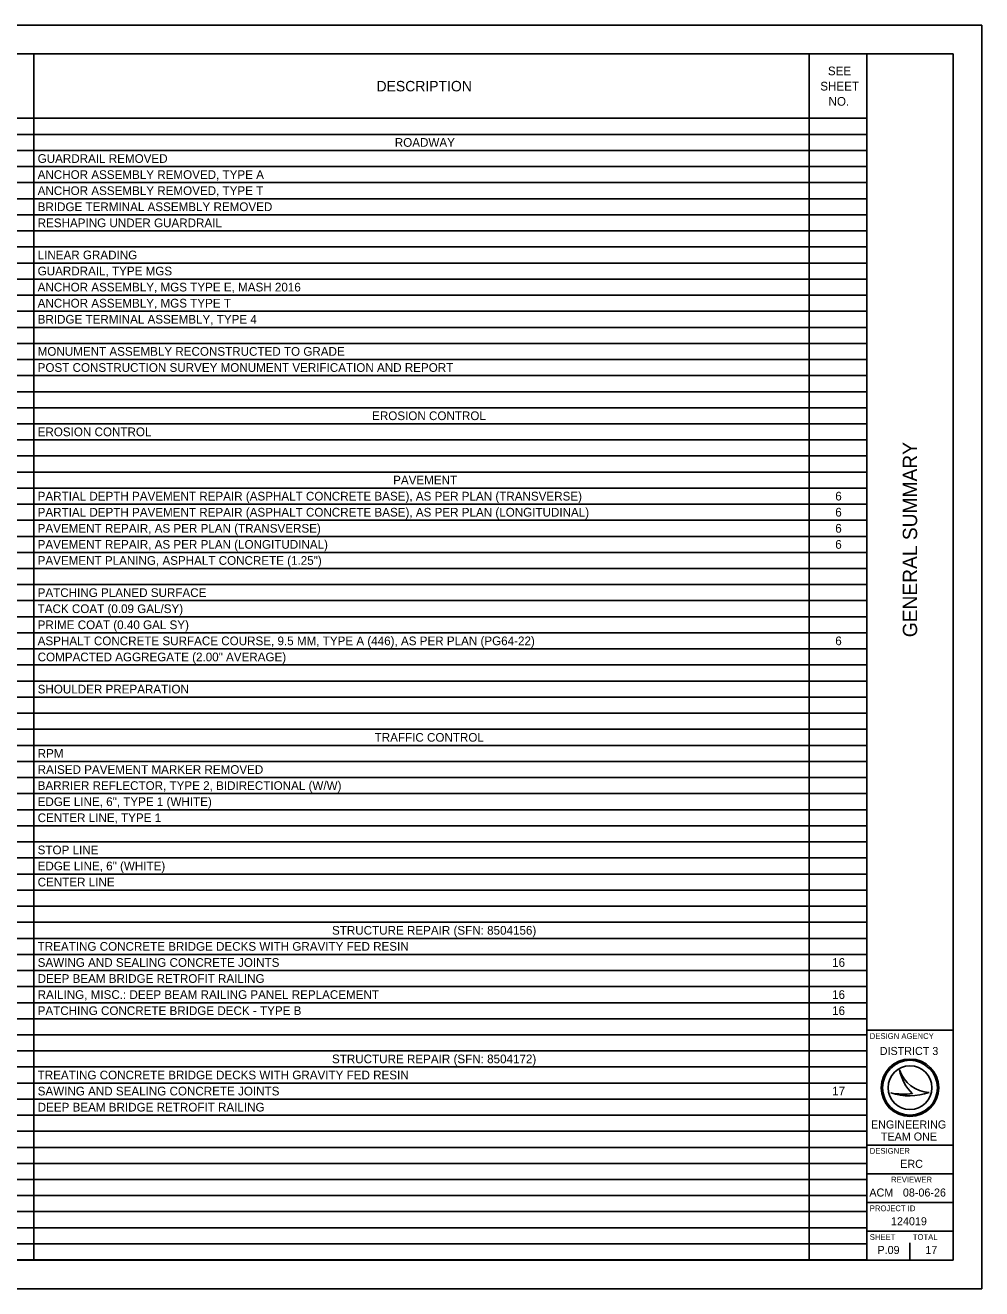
# Model space of a CAD drawing. Extents: x 0 to 34, y 0 to 22.
# Drawn here: x 17.34 to 34, y 0 to 22 of the extents above; entities that cross this region are included whole.
import ezdxf

# ---------------------------------------------------------------- set-up
doc = ezdxf.new("R2010")
doc.units = 0
for name, color, linetype in [('SH_Border', 7, 'Continuous'), ('SH_Cut_Line', 7, 'Continuous'), ('SH_Data', 7, 'Continuous')]:
    doc.layers.add(name, color=color, linetype=linetype)

msp = doc.modelspace()

# ---------------------------------------------------------------- linework, layer by layer
at = {"layer": 'SH_Border'}
for p, q in [((32, 0.5), (32, 21.5)), ((32, 4.5), (33.5, 4.5)), ((32, 2.5), (33.5, 2.5)), ((32, 2), (33.5, 2)), ((32, 1.5), (33.5, 1.5)), ((32, 1), (33.5, 1))]:
    msp.add_line(p, q, dxfattribs=at)
msp.add_lwpolyline([(1.5, 21.5), (33.5, 21.5), (33.5, 0.5), (1.5, 0.5)], close=True, dxfattribs=at)
at = {"layer": 'SH_Cut_Line'}
msp.add_lwpolyline([(0, 0), (34, 0), (34, 22), (0, 22)], close=True, dxfattribs=at)
at = {"layer": 'SH_Data'}
for p, q in [((1.5, 21.5), (32.001, 21.5)), ((17.492, 21.5), (17.492, 0.502)), ((30.997, 21.5), (30.997, 0.502)), ((32.001, 21.5), (32.001, 0.502)), ((1.5, 20.38), (32.001, 20.38)), ((1.5, 20.1), (32.001, 20.1)), ((1.5, 19.82), (32.001, 19.82)), ((1.5, 19.54), (32.001, 19.54)), ((1.5, 19.26), (32.001, 19.26)), ((1.5, 18.98), (32.001, 18.98)), ((1.5, 18.7), (32.001, 18.7)), ((1.5, 18.42), (32.001, 18.42)), ((1.5, 18.14), (32.001, 18.14)), ((1.5, 17.86), (32.001, 17.86)), ((1.5, 17.58), (32.001, 17.58)), ((1.5, 17.3), (32.001, 17.3)), ((1.5, 17.02), (32.001, 17.02)), ((1.5, 16.74), (32.001, 16.74)), ((1.5, 16.46), (32.001, 16.46)), ((1.5, 16.18), (32.001, 16.18)), ((1.5, 15.9), (32.001, 15.9)), ((1.5, 15.62), (32.001, 15.62)), ((1.5, 15.34), (32.001, 15.34)), ((1.5, 15.061), (32.001, 15.061)), ((1.5, 14.781), (32.001, 14.781)), ((1.5, 14.501), (32.001, 14.501)), ((1.5, 14.221), (32.001, 14.221)), ((1.5, 13.941), (32.001, 13.941)), ((1.5, 13.661), (32.001, 13.661)), ((1.5, 13.381), (32.001, 13.381)), ((1.5, 13.101), (32.001, 13.101)), ((1.5, 12.821), (32.001, 12.821)), ((1.5, 12.541), (32.001, 12.541)), ((1.5, 12.261), (32.001, 12.261)), ((1.5, 11.981), (32.001, 11.981)), ((1.5, 11.701), (32.001, 11.701)), ((1.5, 11.421), (32.001, 11.421)), ((1.5, 11.141), (32.001, 11.141)), ((1.5, 10.861), (32.001, 10.861)), ((1.5, 10.581), (32.001, 10.581)), ((1.5, 10.301), (32.001, 10.301)), ((1.5, 10.021), (32.001, 10.021)), ((1.5, 9.741), (32.001, 9.741)), ((1.5, 9.461), (32.001, 9.461)), ((1.5, 9.181), (32.001, 9.181)), ((1.5, 8.901), (32.001, 8.901)), ((1.5, 8.621), (32.001, 8.621)), ((1.5, 8.341), (32.001, 8.341)), ((1.5, 8.061), (32.001, 8.061)), ((1.5, 7.781), (32.001, 7.781)), ((1.5, 7.501), (32.001, 7.501)), ((1.5, 7.221), (32.001, 7.221)), ((1.5, 6.941), (32.001, 6.941)), ((1.5, 6.661), (32.001, 6.661)), ((1.5, 6.381), (32.001, 6.381)), ((1.5, 6.101), (32.001, 6.101)), ((1.5, 5.821), (32.001, 5.821)), ((1.5, 5.541), (32.001, 5.541)), ((1.5, 5.261), (32.001, 5.261)), ((1.5, 4.981), (32.001, 4.981)), ((1.5, 4.701), (32.001, 4.701)), ((1.5, 4.421), (32.001, 4.421)), ((1.5, 4.141), (32.001, 4.141)), ((1.5, 3.861), (32.001, 3.861)), ((32.567, 3.81), (32.567, 3.81)), ((1.5, 3.581), (32.001, 3.581)), ((1.5, 3.301), (32.001, 3.301)), ((32.417, 3.41), (32.417, 3.41)), ((32.75, 3.5), (32.75, 3.5)), ((33.087, 3.419), (33.087, 3.419)), ((1.5, 3.021), (32.001, 3.021)), ((1.5, 2.741), (32.001, 2.741)), ((1.5, 2.461), (32.001, 2.461)), ((1.5, 2.182), (32.001, 2.182)), ((1.5, 1.902), (32.001, 1.902)), ((1.5, 1.622), (32.001, 1.622)), ((1.5, 1.342), (32.001, 1.342)), ((1.5, 1.062), (32.001, 1.062)), ((1.5, 0.782), (32.001, 0.782)), ((32.375, 0.675), (32.375, 0.675)), ((32.75, 0.5), (32.75, 0.8)), ((1.5, 0.502), (32.001, 0.502))]:
    msp.add_line(p, q, dxfattribs=at)
for radius in [0.5, 0.477, 0.477, 0.382]:
    msp.add_circle((32.75, 3.5), radius, dxfattribs=at)
for centre, radius, start, end in [((33.116, 3.998), 0.58, 198.9257, 198.9319), ((33.347, 3.97), 0.796, 191.6379, 191.6421), ((33.116, 3.998), 0.58, 198.9319, 267.1657), ((33.347, 3.97), 0.796, 191.6421, 226.0947), ((32.739, 4.37), 1.013, 251.4576, 290.0832), ((32.648, 4.654), 1.266, 259.4964, 259.4995), ((32.739, 4.37), 1.013, 251.4527, 251.4576), ((32.648, 4.654), 1.266, 259.4995, 276.6672)]:
    msp.add_arc(centre, radius, start, end, dxfattribs=at)

# ---------------------------------------------------------------- texts
for s, height, p in [('SEE ', 0.1515, (31.321, 21.129)), ('DESCRIPTION', 0.18182, (23.459, 20.849)), ('SHEET ', 0.1515, (31.188, 20.864)), ('NO.', 0.1515, (31.332, 20.599)), ('ROADWAY', 0.1515, (23.778, 19.884)), ('GUARDRAIL REMOVED', 0.15152, (17.558, 19.604)), ('ANCHOR ASSEMBLY REMOVED, TYPE A', 0.15152, (17.558, 19.324)), ('ANCHOR ASSEMBLY REMOVED, TYPE T', 0.15152, (17.558, 19.044)), ('BRIDGE TERMINAL ASSEMBLY REMOVED', 0.15152, (17.558, 18.764)), ('RESHAPING UNDER GUARDRAIL', 0.15152, (17.558, 18.484)), ('LINEAR GRADING', 0.15152, (17.558, 17.925)), ('GUARDRAIL, TYPE MGS', 0.15152, (17.558, 17.645)), ('ANCHOR ASSEMBLY, MGS TYPE E, MASH 2016', 0.15152, (17.558, 17.365)), ('ANCHOR ASSEMBLY, MGS TYPE T', 0.15152, (17.558, 17.085)), ('BRIDGE TERMINAL ASSEMBLY, TYPE 4', 0.15152, (17.558, 16.805)), ('MONUMENT ASSEMBLY RECONSTRUCTED TO GRADE', 0.15152, (17.558, 16.245)), ('POST CONSTRUCTION SURVEY MONUMENT VERIFICATION AND REPORT', 0.15152, (17.558, 15.965)), ('EROSION CONTROL', 0.15152, (23.383, 15.125)), ('EROSION CONTROL', 0.15152, (17.558, 14.845)), ('PAVEMENT', 0.1515, (23.749, 14.005)), ('PARTIAL DEPTH PAVEMENT REPAIR (ASPHALT CONCRETE BASE), AS PER PLAN (TRANSVERSE)', 0.15152, (17.558, 13.725)), ('6', 0.152, (31.449, 13.725)), ('PARTIAL DEPTH PAVEMENT REPAIR (ASPHALT CONCRETE BASE), AS PER PLAN (LONGITUDINAL)', 0.15152, (17.558, 13.445)), ('6', 0.152, (31.449, 13.445)), ('PAVEMENT REPAIR, AS PER PLAN (TRANSVERSE)', 0.15152, (17.558, 13.165)), ('6', 0.152, (31.449, 13.165)), ('PAVEMENT REPAIR, AS PER PLAN (LONGITUDINAL)', 0.15152, (17.558, 12.885)), ('6', 0.152, (31.449, 12.885)), ('PAVEMENT PLANING, ASPHALT CONCRETE (1.25")', 0.15152, (17.558, 12.605)), ('PATCHING PLANED SURFACE', 0.15152, (17.558, 12.045)), ('TACK COAT (0.09 GAL/SY)', 0.15152, (17.558, 11.765)), ('PRIME COAT (0.40 GAL SY)', 0.15152, (17.558, 11.485)), ('ASPHALT CONCRETE SURFACE COURSE, 9.5 MM, TYPE A (446), AS PER PLAN (PG64-22)', 0.15152, (17.558, 11.205)), ('6', 0.152, (31.449, 11.205)), ('COMPACTED AGGREGATE (2.00" AVERAGE)', 0.15152, (17.558, 10.925)), ('SHOULDER PREPARATION', 0.15152, (17.558, 10.365)), ('TRAFFIC CONTROL', 0.15152, (23.427, 9.525)), ('RPM', 0.1515, (17.558, 9.245)), ('RAISED PAVEMENT MARKER REMOVED', 0.15152, (17.558, 8.965)), ('BARRIER REFLECTOR, TYPE 2, BIDIRECTIONAL (W/W)', 0.15152, (17.558, 8.685)), ('EDGE LINE, 6", TYPE 1 (WHITE)', 0.15152, (17.558, 8.405)), ('CENTER LINE, TYPE 1', 0.15152, (17.558, 8.125)), ('STOP LINE', 0.1515, (17.558, 7.565)), ('EDGE LINE, 6" (WHITE)', 0.15152, (17.558, 7.285)), ('CENTER LINE', 0.15152, (17.558, 7.005)), ('STRUCTURE REPAIR (SFN: 8504156)', 0.15152, (22.684, 6.165)), ('TREATING CONCRETE BRIDGE DECKS WITH GRAVITY FED RESIN', 0.15152, (17.558, 5.885)), ('SAWING AND SEALING CONCRETE JOINTS', 0.15152, (17.558, 5.605)), ('16', 0.1515, (31.394, 5.605)), ('DEEP BEAM BRIDGE RETROFIT RAILING', 0.15152, (17.558, 5.326)), ('RAILING, MISC.: DEEP BEAM RAILING PANEL REPLACEMENT', 0.15152, (17.558, 5.046)), ('16', 0.1515, (31.394, 5.046)), ('PATCHING CONCRETE BRIDGE DECK - TYPE B', 0.15152, (17.558, 4.766)), ('16', 0.1515, (31.394, 4.766)), ('DESIGN AGENCY', 0.1, (32.05, 4.35)), ('DISTRICT 3', 0.14, (32.224, 4.07)), ('STRUCTURE REPAIR (SFN: 8504172)', 0.15152, (22.684, 3.926)), ('TREATING CONCRETE BRIDGE DECKS WITH GRAVITY FED RESIN', 0.15152, (17.558, 3.646)), ('SAWING AND SEALING CONCRETE JOINTS', 0.15152, (17.558, 3.366)), ('17', 0.1515, (31.395, 3.366)), ('DEEP BEAM BRIDGE RETROFIT RAILING', 0.15152, (17.558, 3.086)), ('ENGINEERING', 0.14, (32.071, 2.79)), ('TEAM ONE', 0.14, (32.244, 2.58)), ('DESIGNER', 0.1, (32.05, 2.35)), ('ERC', 0.14, (32.581, 2.105)), ('REVIEWER', 0.1, (32.422, 1.85)), ('ACM', 0.14, (32.043, 1.605)), ('08-06-26', 0.14, (32.627, 1.605)), ('PROJECT ID', 0.1, (32.05, 1.35)), ('124019', 0.14, (32.42, 1.105)), ('SHEET', 0.1, (32.05, 0.85)), ('TOTAL', 0.1, (32.8, 0.85)), ('P.09', 0.14, (32.184, 0.605)), ('17', 0.14, (33.018, 0.605))]:
    msp.add_text(s, height=height, dxfattribs=at).set_placement(p)
msp.add_text('GENERAL SUMMARY', height=0.25, rotation=90, dxfattribs=at).set_placement((32.875, 11.344))

doc.saveas('drawing.dxf')
